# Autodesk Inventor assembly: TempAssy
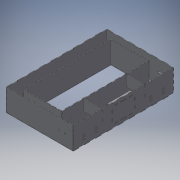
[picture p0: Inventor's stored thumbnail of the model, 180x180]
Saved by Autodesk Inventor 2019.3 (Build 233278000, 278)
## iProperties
Created: 2020-03
Part Number: TempAssy
Document SubType Name: Assembly
Designer: KrystynWikoff
Author: KrystynWikoff
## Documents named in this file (10)
- C:\Users\KrystynWikoff\Desktop\UCF\2020\Frame\Acrylicv2\TempAssy.iam
- C:\Users\KrystynWikoff\Desktop\UCF\2020\Frame\Acrylicv2\FrontFace.ipt
- C:\Users\KrystynWikoff\Desktop\UCF\2020\Frame\Acrylicv2\SideLeft.ipt
- C:\Users\KrystynWikoff\Desktop\UCF\2020\Frame\Acrylicv2\SideRight.ipt
- C:\Users\KrystynWikoff\Desktop\UCF\2020\Frame\Acrylicv2\OutsideTop.ipt
- C:\Users\KrystynWikoff\Desktop\UCF\2020\Frame\Acrylicv2\InsideSides.ipt
- C:\Users\KrystynWikoff\Desktop\UCF\2020\Frame\Acrylicv2\InsideTop8Holes.ipt
- C:\Users\KrystynWikoff\Desktop\UCF\2020\Frame\Acrylicv2\InsideBottom8Holes.ipt
- C:\Users\KrystynWikoff\Desktop\UCF\2020\Frame\Acrylicv2\InsideTop8HolesLaserSupports.ipt
- C:\Users\KrystynWikoff\Desktop\UCF\2020\Frame\Acrylicv2\BottomAssy.iam
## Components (11 placed, 9 different names)
1. FrontFace:1 — Flush:1, Flush:2, Flush:3, Mate:1, Flush:4, Mate:2, Mate:4, Flush:7, Flush:8, Flush:9, Mate:5, Mate:8, Flush:13, Mate:9, Mate:10, Flush:14, Mate:11, Flush:15, Mate:12, Mate:13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
2. SideLeft:1 — Mate:1, Flush:4, Mate:2, Flush:23
3. SideRight:1 — Flush:8, Flush:9, Mate:5, Flush:10
4. OutsideTop:1 — Mate:4, Flush:7, Flush:10
5. InsideSides:1 — Mate:8, Flush:13, Mate:9
6. InsideSides:2 — Mate:10, Flush:14, Mate:11, Flush:20, Mate:17
7. InsideTop8Holes:1 — Flush:15, Mate:12, Mate:13, Mate:16
8. InsideTop8HolesLaserSupports:1 — Mate:15, Flush:18, Flush:19, Flush:20, Mate:17
9. InsideTop8HolesLaserSupports:2 — Mate:15, Flush:18, Flush:19, Mate:16
10. InsideBottom8Holes:1 — Flush:21, Flush:22, Mate:18
11. BottomAssy:1 [sub-assembly] — Flush:23, Flush:24, Flush:25
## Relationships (33: Flush 19, Mate 14)
- Flush:1: FrontFace:1
- Flush:2: FrontFace:1
- Flush:3: FrontFace:1
- Mate:1: FrontFace:1 ↔ SideLeft:1
- Flush:4: FrontFace:1 ↔ SideLeft:1
- Mate:2: FrontFace:1 ↔ SideLeft:1
- Mate:4: FrontFace:1 ↔ OutsideTop:1
- Flush:7: FrontFace:1 ↔ OutsideTop:1
- Flush:8: FrontFace:1 ↔ SideRight:1
- Flush:9: FrontFace:1 ↔ SideRight:1
- Mate:5: FrontFace:1 ↔ SideRight:1
- Flush:10: SideRight:1 ↔ OutsideTop:1
- Mate:8: FrontFace:1 ↔ InsideSides:1
- Flush:13: FrontFace:1 ↔ InsideSides:1
- Mate:9: FrontFace:1 ↔ InsideSides:1
- Mate:10: FrontFace:1 ↔ InsideSides:2
- Flush:14: FrontFace:1 ↔ InsideSides:2
- Mate:11: FrontFace:1 ↔ InsideSides:2
- Flush:15: FrontFace:1 ↔ InsideTop8Holes:1
- Mate:12: FrontFace:1 ↔ InsideTop8Holes:1
- Mate:13: FrontFace:1 ↔ InsideTop8Holes:1
- Mate:15: InsideTop8HolesLaserSupports:1 ↔ InsideTop8HolesLaserSupports:2
- Flush:18: InsideTop8HolesLaserSupports:1 ↔ InsideTop8HolesLaserSupports:2
- Flush:19: InsideTop8HolesLaserSupports:1 ↔ InsideTop8HolesLaserSupports:2
- Mate:16: InsideTop8Holes:1 ↔ InsideTop8HolesLaserSupports:2
- Flush:20: InsideSides:2 ↔ InsideTop8HolesLaserSupports:1
- Mate:17: InsideSides:2 ↔ InsideTop8HolesLaserSupports:1
- Flush:21: FrontFace:1 ↔ InsideBottom8Holes:1
- Flush:22: FrontFace:1 ↔ InsideBottom8Holes:1
- Mate:18: FrontFace:1 ↔ InsideBottom8Holes:1
- Flush:23: SideLeft:1 ↔ BottomAssy:1
- Flush:24: FrontFace:1 ↔ BottomAssy:1
- Flush:25: FrontFace:1 ↔ BottomAssy:1
